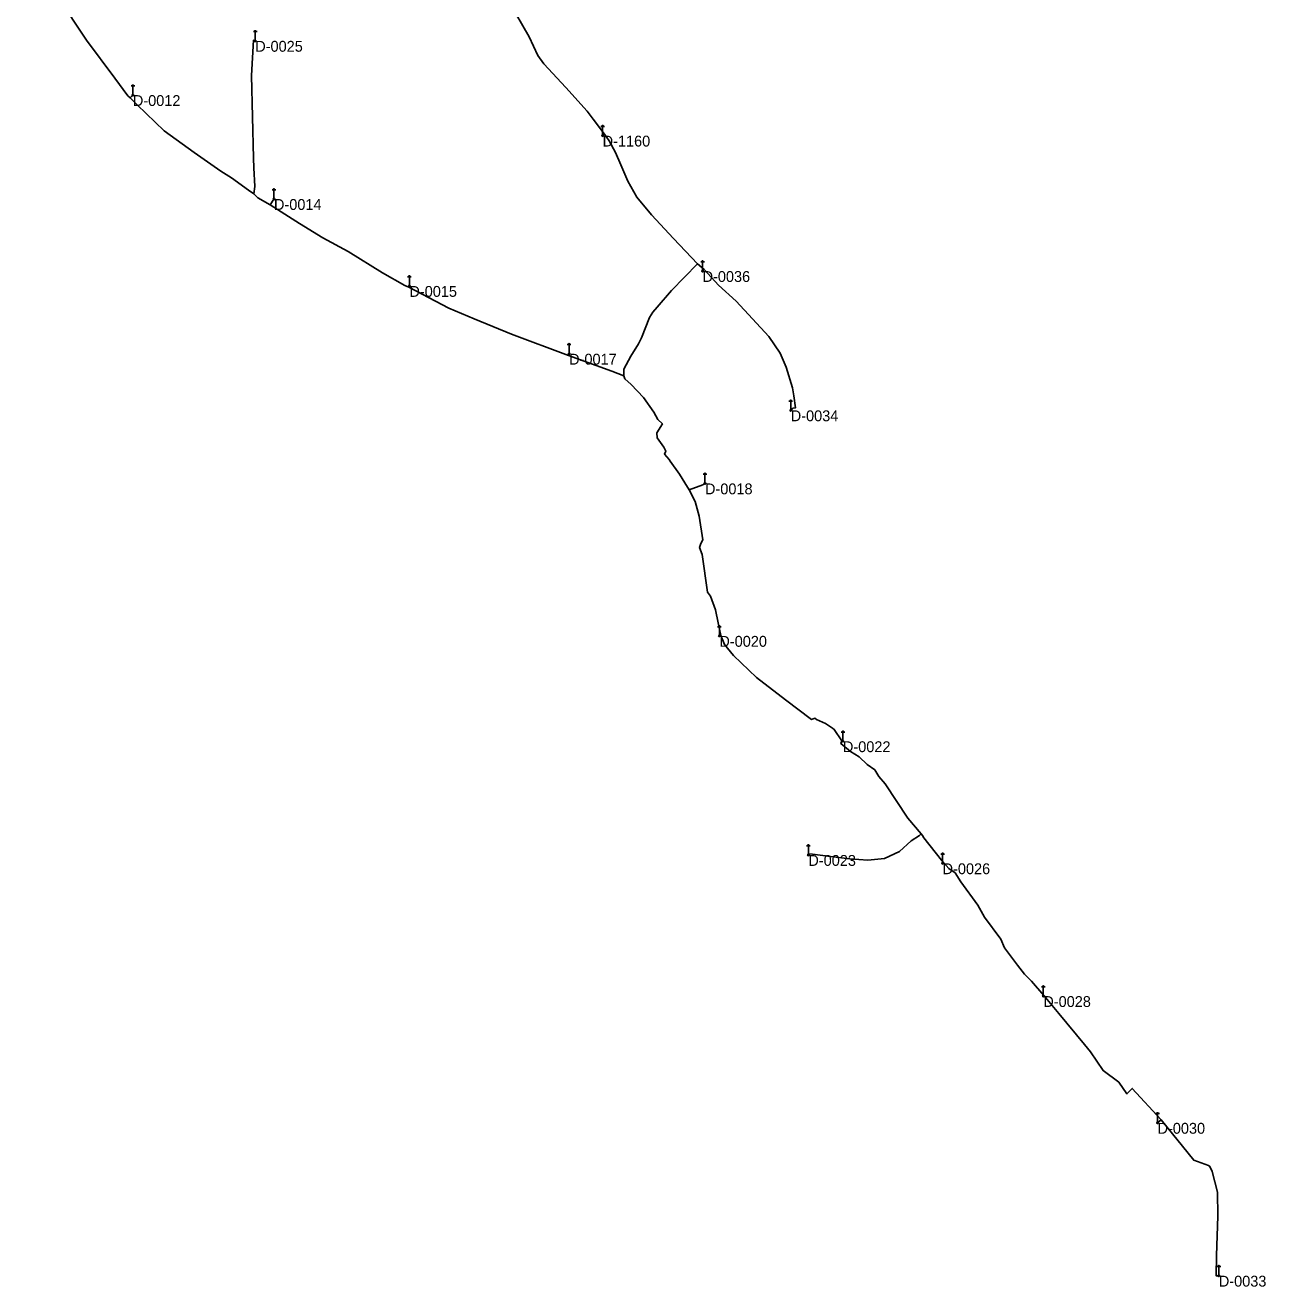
# Model space of a CAD drawing. Extents: x -729889 to -691139, y -995431 to -974354.
# Drawn here: x -727428.7 to -727085.5, y -978076.8 to -977727.9 of the extents above; entities that cross this region are included whole.
import ezdxf

# ---------------------------------------------------------------- set-up
doc = ezdxf.new("R2010")
doc.units = 0
for name, color, linetype in [('Atributy', 7, 'Continuous'), ('Skutečně zaměřené kabelové vedení', 7, 'Continuous'), ('Světelný bod na stožáru sadovém', 7, 'Continuous')]:
    doc.layers.add(name, color=color, linetype=linetype)

# ---------------------------------------------------------------- blocks, each defined once
blk = doc.blocks.new('6.571')
at = {"layer": 'Světelný bod na stožáru sadovém'}
for p, q in [((-0.51, 2.54), (0.51, 2.54)), ((0, 2.54), (0, 0.2))]:
    blk.add_line(p, q, dxfattribs=at)
for points in [[(0.25, 2.54), (0.25, 2.56), (0.25, 2.58), (0.24, 2.6), (0.24, 2.62), (0.23, 2.64), (0.22, 2.66), (0.21, 2.69), (0.19, 2.7), (0.18, 2.72), (0.16, 2.73), (0.15, 2.75), (0.13, 2.76), (0.11, 2.77), (0.09, 2.78), (0.07, 2.78), (0.05, 2.79), (0.02, 2.79), (0, 2.79), (-0.02, 2.79), (-0.05, 2.79), (-0.07, 2.78), (-0.09, 2.78), (-0.11, 2.77), (-0.13, 2.76), (-0.15, 2.75), (-0.16, 2.73), (-0.18, 2.72), (-0.19, 2.7), (-0.21, 2.69), (-0.22, 2.66), (-0.23, 2.64), (-0.24, 2.62), (-0.24, 2.6), (-0.25, 2.58), (-0.25, 2.56), (-0.25, 2.54)], [(-0.2, 0), (-0.17, -0.1), (-0.08, -0.18), (0.04, -0.19), (0.13, -0.14), (0.19, -0.05), (0.18, 0.07), (0.12, 0.15), (0.02, 0.19), (-0.09, 0.17), (-0.17, 0.09), (-0.18, -0.01), (-0.15, -0.1), (-0.06, -0.17), (0.04, -0.17), (0.12, -0.12), (0.17, -0.03), (0.16, 0.08), (0.1, 0.14), (0.01, 0.17), (-0.09, 0.14), (-0.15, 0.07), (-0.16, -0.01), (-0.12, -0.1), (-0.04, -0.15), (0.04, -0.15), (0.12, -0.1), (0.15, -0.01), (0.14, 0.07), (0.08, 0.13), (-0.01, 0.15), (-0.09, 0.12), (-0.13, 0.06), (-0.14, -0.02), (-0.1, -0.1), (-0.03, -0.13), (0.04, -0.13), (0.11, -0.08), (0.13, 0), (0.12, 0.07), (0.06, 0.12), (-0.02, 0.13), (-0.08, 0.1), (-0.12, 0.05), (-0.12, -0.03), (-0.08, -0.09), (-0.02, -0.11), (0.05, -0.11), (0.1, -0.06), (0.11, 0.01), (0.1, 0.06), (0.05, 0.11), (-0.02, 0.11), (-0.07, 0.09), (-0.1, 0.04), (-0.1, -0.03), (-0.06, -0.08), (-0.02, -0.1), (0.05, -0.08), (0.09, -0.04), (0.1, 0.01), (0.08, 0.06), (0.03, 0.09), (-0.02, 0.09), (-0.06, 0.07), (-0.08, 0.02), (-0.08, -0.03), (-0.05, -0.06), (-0.01, -0.08), (0.04, -0.06), (0.07, -0.03), (0.07, 0.01), (0.06, 0.05), (0.02, 0.07), (-0.02, 0.07), (-0.05, 0.05), (-0.07, 0.02), (-0.06, -0.03), (-0.04, -0.05), (0, -0.06), (0.04, -0.04), (0.05, -0.02), (0.06, 0.01), (0.04, 0.04), (0.01, 0.05), (-0.02, 0.05), (-0.04, 0.04), (-0.05, 0.01), (-0.04, -0.02), (-0.02, -0.03), (0.01, -0.04), (0.03, -0.03), (0.04, -0.01), (0.04, 0.01), (0.02, 0.03), (0.01, 0.04), (-0.01, 0.03), (-0.02, 0.02), (-0.03, 0.01), (-0.02, -0.01), (-0.01, -0.02)], [(-0.01, -0.02), (0.01, -0.02), (0.01, -0.01), (0.02, 0), (0.02, 0.01), (0.01, 0.02), (0, 0.02), (-0.01, 0.01), (-0.01, 0.01), (-0.01, 0.01)]]:
    blk.add_lwpolyline(points, dxfattribs=at)
blk.add_circle((0, 0), 0.203, dxfattribs=at)

msp = doc.modelspace()

# ---------------------------------------------------------------- linework, layer by layer
at = {"layer": 'Skutečně zaměřené kabelové vedení'}
for points in [[(-727399.65, -977747.95), (-727400.26, -977747.34), (-727403.9, -977742.49), (-727411.74, -977731.97), (-727415.57, -977726.18), (-727418.03, -977722.01), (-727419.77, -977718.9), (-727424.02, -977711.89), (-727428.66, -977705.16), (-727427.38, -977704.28)], [(-727268.46, -977758), (-727271.53, -977753.83), (-727273.26, -977751.6), (-727279.15, -977745.07), (-727285.26, -977738.54), (-727286.86, -977736.27), (-727289.31, -977731.06), (-727294.89, -977721.32), (-727296.02, -977719.44), (-727296.39, -977719.66)], [(-727360.88, -977777.52), (-727364.31, -977775.55), (-727365.47, -977774.5), (-727365.13, -977772.45), (-727365.39, -977767.32), (-727365.55, -977764.66), (-727366.09, -977741.73), (-727365.54, -977731.99), (-727365.04, -977732.17)], [(-727365.47, -977774.5), (-727366.91, -977773.5), (-727371.63, -977770.06), (-727374.53, -977768.23), (-727381.89, -977763.07), (-727390.24, -977757.08), (-727397.72, -977749.87), (-727399.65, -977747.95), (-727398.89, -977747.18)], [(-727242.69, -977793.82), (-727249.37, -977786.81), (-727255.45, -977780.3), (-727259.45, -977775.4), (-727261.94, -977770.96), (-727263.96, -977766.46), (-727265.4, -977763.07), (-727267.16, -977759.86), (-727268.46, -977758), (-727268.95, -977758.39)], [(-727322.59, -977800.34), (-727323.63, -977799.8), (-727329.85, -977796.35), (-727339.33, -977790.43), (-727346.34, -977786.65), (-727352.76, -977782.72), (-727360.88, -977777.52), (-727359.86, -977775.93)], [(-727263.08, -977824.83), (-727263.13, -977822.96), (-727261.14, -977819.4), (-727259.07, -977816), (-727258.17, -977814.31), (-727256.01, -977808.67), (-727255.09, -977807.25), (-727253.84, -977805.81), (-727249.88, -977801.19), (-727242.69, -977793.82), (-727240.84, -977795.46), (-727241.31, -977795.85)], [(-727240.84, -977795.46), (-727236.87, -977799.72), (-727231.98, -977804.22), (-727223.01, -977813.95), (-727219.81, -977818.55), (-727218.15, -977822.48), (-727216.47, -977828.15), (-727216.11, -977830.34), (-727215.6, -977833.64), (-727216.34, -977833.82), (-727216.92, -977834.38)], [(-727278.22, -977818.72), (-727278.4, -977819.21), (-727294.18, -977813.34), (-727304.5, -977809.04), (-727311.47, -977806.09), (-727322.59, -977800.34), (-727322.4, -977799.97)], [(-727246.17, -977854.46), (-727247.72, -977852.03), (-727250.24, -977848.45), (-727250.58, -977847.97), (-727251.81, -977846.5), (-727251.5, -977845.68), (-727251.99, -977844.57), (-727253.86, -977841.96), (-727253.96, -977840.57), (-727252.43, -977838.14), (-727253.71, -977836.94), (-727254.83, -977834.86), (-727257.69, -977830.86), (-727261.09, -977827.24), (-727262.81, -977825.65), (-727263.08, -977824.83), (-727266.45, -977823.5), (-727278.4, -977819.21)], [(-727236.25, -977896.67), (-727236.99, -977893.12), (-727237.7, -977889.59), (-727239.11, -977885.77), (-727239.93, -977884.7), (-727241.39, -977874.21), (-727242.15, -977872.34), (-727241.76, -977871.2), (-727241.22, -977870.17), (-727242.25, -977863.61), (-727243.35, -977859.63), (-727245.01, -977856.38), (-727246.17, -977854.46)], [(-727245.01, -977856.38), (-727241.2, -977855.02), (-727240.64, -977854.59)], [(-727202.77, -977925.75), (-727204.89, -977922.65), (-727205.39, -977922.32), (-727207.33, -977921.03), (-727209.77, -977919.93), (-727210.29, -977919.56), (-727211.22, -977919.87), (-727218.39, -977914.47), (-727226.43, -977908.27), (-727232.72, -977902.22), (-727235.23, -977899.17), (-727236.25, -977896.67), (-727236.66, -977896.76)], [(-727180.81, -977951.54), (-727184.51, -977947.16), (-727190.82, -977937.65), (-727192.58, -977935.69), (-727193.7, -977933.79), (-727195.74, -977932.32), (-727198.04, -977930.23), (-727200.42, -977928.79), (-727203.03, -977926.57), (-727202.77, -977925.75), (-727202.49, -977925.91)], [(-727174.67, -977959.45), (-727175.25, -977958.8), (-727180.07, -977952.65), (-727180.46, -977951.95), (-727180.81, -977951.54), (-727181.31, -977951.96), (-727183.65, -977953.49), (-727186.85, -977956.42), (-727191, -977958.36), (-727195.64, -977958.77), (-727200.61, -977958.4), (-727205.9, -977957.81), (-727210.88, -977957.16), (-727211.97, -977957.08), (-727212.05, -977957.37)], [(-727146.9, -977996.27), (-727150.33, -977992.27), (-727152.25, -977990.37), (-727154.17, -977987.84), (-727157.75, -977983.06), (-727158.77, -977980.69), (-727163.34, -977974.57), (-727165.2, -977971.24), (-727169.86, -977964.83), (-727171.44, -977962.32), (-727173.19, -977961.1), (-727174.67, -977959.45), (-727174.92, -977959.67)], [(-727114.47, -978030.59), (-727122.48, -978021.94), (-727123.92, -978023.46), (-727126.18, -978020.23), (-727130.53, -978017.02), (-727134.05, -978011.83), (-727135.68, -978009.8), (-727142.74, -978001.19), (-727146.48, -977996.76), (-727146.9, -977996.27), (-727147.06, -977996.4)], [(-727098.51, -978073.75), (-727099.25, -978073.74), (-727099.16, -978068.13), (-727098.77, -978057.32), (-727098.86, -978050.62), (-727100.33, -978044.88), (-727101, -978043.5), (-727101.38, -978043.22), (-727105.47, -978041.76), (-727114.47, -978030.59), (-727115.47, -978031.46)]]:
    msp.add_lwpolyline(points, dxfattribs=at)

# ---------------------------------------------------------------- block references
at = {"layer": 'Světelný bod na stožáru sadovém', "xscale": 1.0016949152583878, "yscale": 1.0016949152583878}
for p in [(-727365.04, -977732.17), (-727398.89, -977747.18), (-727268.95, -977758.39), (-727359.86, -977775.93), (-727241.31, -977795.85), (-727322.4, -977799.97), (-727278.22, -977818.72), (-727216.92, -977834.38), (-727240.64, -977854.59), (-727236.66, -977896.76), (-727202.49, -977925.91), (-727212.05, -977957.37), (-727174.92, -977959.67), (-727147.06, -977996.4), (-727115.47, -978031.46), (-727098.51, -978073.75)]:
    msp.add_blockref('6.571', p, dxfattribs=at)

# ---------------------------------------------------------------- texts
at = {"layer": 'Atributy'}
for s, p in [('D-0025', (-727365.04, -977735.18)), ('D-0012', (-727398.89, -977750.19)), ('D-1160', (-727268.95, -977761.4)), ('D-0014', (-727359.86, -977778.94)), ('D-0036', (-727241.31, -977798.86)), ('D-0015', (-727322.4, -977802.98)), ('D-0017', (-727278.22, -977821.73)), ('D-0034', (-727216.92, -977837.39)), ('D-0018', (-727240.64, -977857.6)), ('D-0020', (-727236.66, -977899.77)), ('D-0022', (-727202.49, -977928.92)), ('D-0023', (-727212.05, -977960.38)), ('D-0026', (-727174.92, -977962.68)), ('D-0028', (-727147.06, -977999.41)), ('D-0030', (-727115.47, -978034.47)), ('D-0033', (-727098.51, -978076.76))]:
    msp.add_text(s, height=3, dxfattribs=at).set_placement(p)

doc.saveas('drawing.dxf')
